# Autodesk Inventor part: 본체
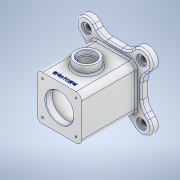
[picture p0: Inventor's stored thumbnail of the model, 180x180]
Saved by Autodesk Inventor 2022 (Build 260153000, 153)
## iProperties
Created: 2022-05
Part Number: 본체
Material: 알루미늄 6061
Document SubType Name: Modeling
Designer: admin
Mass: 1076.28 g
Surface Area: 879.96 cm^2
Volume: 398.62 cm^3
Density: 2.7 g/cm^3
Appearance: 알루미늄 - 평지
Author: admin
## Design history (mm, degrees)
sketch "스케치1"
  geometry: L1 (-40, 40)-(40, 40); L2 (40, 40)-(40, -40); L3 (40, -40)-(-40, -40); L4 (-40, -40)-(-40, 40); L5 (-40, 40)-(40, -40); L6 (40, 40)-(-40, -40); 1 further point
  constraints: 12 end point, 2 midpoint, 2 parallel, 1 horizontal, 1 perpendicular
  dimensions: "d0" = 80 distance of L1.start L1.end; "d1" = 80 distance of L1.end L2.end
extrude "돌출1" new body sketch "스케치1" stored distance "d2" = 98; taper "d3" = 0 deg
sketch "스케치2"
  geometry: L1 (49, 49)-(-49, 49); L2 (-49, 49)-(-49, -49); L3 (-49, -49)-(49, -49); L4 (49, -49)-(49, 49); L5 (49, 49)-(-49, -49); L6 (-49, 49)-(49, -49); 1 further point
  constraints: 12 end point, 2 midpoint, 2 parallel, 1 horizontal, 1 perpendicular
  dimensions: "d4" = 98 distance of L3.end L1.start; "d5" = 98 distance of L2.end L3.end
extrude "돌출2" join sketch "스케치2" distance "d6" = 12; taper "d7" = 0 deg
sketch "스케치3" dims "d71" = 140
  geometry: L1 (0, 0)-(71.621, 71.621); L2 (-98, 0)-(98, 0) reference; L3 (36.77, 62.225)-(-62.225, -36.77); L4 (62.225, 36.77)-(-36.77, -62.225); L5 (-36.77, 62.225)-(62.225, -36.77); L6 (-62.225, 36.77)-(36.77, -62.225); A1 r 18 centre (49.497, 49.497) between (36.77, 62.225) and (62.225, 36.77); A2 r 18 centre (-49.497, 49.497) between (-62.225, 36.77) and (-36.77, 62.225); A3 r 18 centre (-49.497, -49.497) between (-36.77, -62.225) and (-62.225, -36.77); A4 r 18 centre (49.497, -49.497) between (62.225, -36.77) and (36.77, -62.225); 6 further points
  constraints: 10 end point, 8 point on circle, 8 tangent, 4 centre point, 1 coincident, 1 point on line, 12 other
  dimensions: "d72" = 45 deg angle of L2 L1; "d73" = 36 diameter of A1; "d76" = 360 deg dimension on point (0, 0) A1.centre (derived)
extrude "돌출3" join sketch "스케치3" distance "d10" = 12; taper "d11" = 0 deg
sketch "스케치4"
  geometry: A1 r 18 centre (-49.497, 49.497) between (-36.77, 62.225) and (-62.225, 36.77) reference; 2 further points
  constraints: 1 coincident
hole "구멍1" sketch "스케치4" at (-49.497, 49.497) diameter "d12" = 10; stored, may be unused: countersink angle "d16" = 90 deg, drill point angle "d18" = 0 deg; dims "d13" = 8, "d14" = 18, "d15" = 4, "d17" = 12
sketch "스케치5"
  geometry: L1 (25, 49)-(25, 37); L2 (25, 37)-(32, 37); L3 (35, 34)-(35, -46); L4 (32, -49)-(25, -49); L5 (25, -49)-(25, -61); L6 (-49, -61)-(49, -61) reference; L7 (40, 49)-(-40, 49) reference; L8 (0, -83)-(0, 71) reference; L9 (25, 49)-(0, 49); L10 (0, 49)-(0, -61); L11 (25, -61)-(0, -61); A1 r 3 centre (32, 34) between (35, 34) and (32, 37); A2 r 3 centre (32, -46) between (32, -49) and (35, -46); 2 further points
  constraints: 16 end point, 6 point on line, 4 point on circle, 4 tangent, 3 perpendicular, 2 centre point, 2 midpoint, 1 collinear, 1 equal radius, 1 vertical
  dimensions: "d22" = 50 diameter of L1 L8; "d23" = 70 diameter of L3 L8; "d24" = 12 distance of L1.start L1.end; "d25" = 12 distance of L4.end L5.end; "d26" = 3 radius of A1
revolve "회전1" sketch "스케치5" stored, may be unused: angle "d27" = 90 deg
node "작업 평면1"
sketch "스케치6"
  geometry: C1 r 20 at (0, 0); 1 further point
  constraints: 1 centre point, 1 coincident
  dimensions: "d29" = 40 diameter of C1
extrude "돌출4" join sketch "스케치6" stored distance "d30" = 12; taper "d31" = 0 deg
sketch "스케치7"
  geometry: C1 r 15 at (0, 0); 1 further point
  constraints: 1 centre point, 1 coincident
  dimensions: "d32" = 30 diameter of C1
extrude "돌출5" cut sketch "스케치7" distance "d33" = 8; taper "d34" = 0 deg
sketch "스케치8"
  geometry: C1 r 12.5 at (0, 0); 1 further point
  constraints: 1 centre point, 1 coincident
  dimensions: "d35" = 25 diameter of C1
extrude "돌출6" cut sketch "스케치8" stored distance "d36" = 8; taper "d37" = 0 deg
sketch "스케치9"
  geometry: L1 (-40, 40)-(-40, -40) reference; L2 (40, 40)-(-40, 40) reference; 2 further points
  dimensions: "d38" = 10 distance from line of L1 point (-30, 30); "d39" = 10 distance from line of L2 point (-30, 30)
hole "구멍2" sketch "스케치9" at (-30, 30) diameter "d40" = 3.242; stored, may be unused: countersink angle "d44" = 90 deg, drill point angle "d46" = 118 deg; dims "d41" = 8, "d42" = 18, "d43" = 4, "d45" = 10
sketch "스케치10"
  geometry: L1 (-30, 30)-(30, 30); L2 (30, 30)-(30, -30); L3 (30, -30)-(-30, -30); L4 (-30, -30)-(-30, 30); L5 (-30, 30)-(30, -30); L6 (30, 30)-(-30, -30); C1 r 1.621 at (-30, -30) reference; 2 further points
  constraints: 12 end point, 2 midpoint, 2 parallel, 1 coincident, 1 horizontal, 1 perpendicular
  dimensions: "d50" = 60 distance of L1.end L2.end; "d51" = 60 distance of L2.end L3.end
hole "구멍3" sketch "스케치10" at (-30, -30) diameter "d52" = 3.242; stored, may be unused: countersink angle "d56" = 90 deg, drill point angle "d58" = 118 deg; dims "d53" = 8, "d54" = 4, "d55" = 2, "d57" = 10
fillet "모깎기2" dims "d63" = 10
chamfer "모따기1" distance "d65" = 1; stored, may be unused: second distance "d66" = 2, angle "d67" = 45 deg
sketch "스케치11" dims "d0" = 80, "d1" = 80
  geometry: L1 (60, 0)-(0, 0) reference; L2 (30, 132)-(30, -22) reference; 2 further points
  constraints: 1 point on line, 1 other
  dimensions: "d68" = 10 distance from line of L1 point (30, 10)
feature "엠보싱1" sketch "스케치11" dims "d0" = 80, "d1" = 80, "d69" = 0.5, "d70" = 0
fillet "모깎기4" dims "d78" = 25
fillet "모깎기5" dims "d79" = 3
node "솔리드1"
pattern_circular "원형 패턴1" dims angle "d20" = 360 deg
pattern_circular "원형 패턴2" dims angle "d48" = 360 deg
pattern_circular "원형 패턴3" dims angle "d60" = 360 deg
feature "A9D066F2-1C7D-4E18-AEED-F7BC21143FA4" dims "d12" = 10, "d13" = 8, "d14" = 18, "d15" = 4, "d16" = 90 deg, "d17" = 12, "d18" = 0
other parameters: "d28" = 55
